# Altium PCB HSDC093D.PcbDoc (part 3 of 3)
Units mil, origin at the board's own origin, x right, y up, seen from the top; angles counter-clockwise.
Board outline 4360 x 2202.42 mil, 6 copper layers (Top Layer, GND1, VCC1, VCC2, GND2, Bottom Layer), stack 84.434 mil thick; 280 components, 182 nets, 800 pads, 401 vias.
Unrouted connection lines stored in the file: 5.
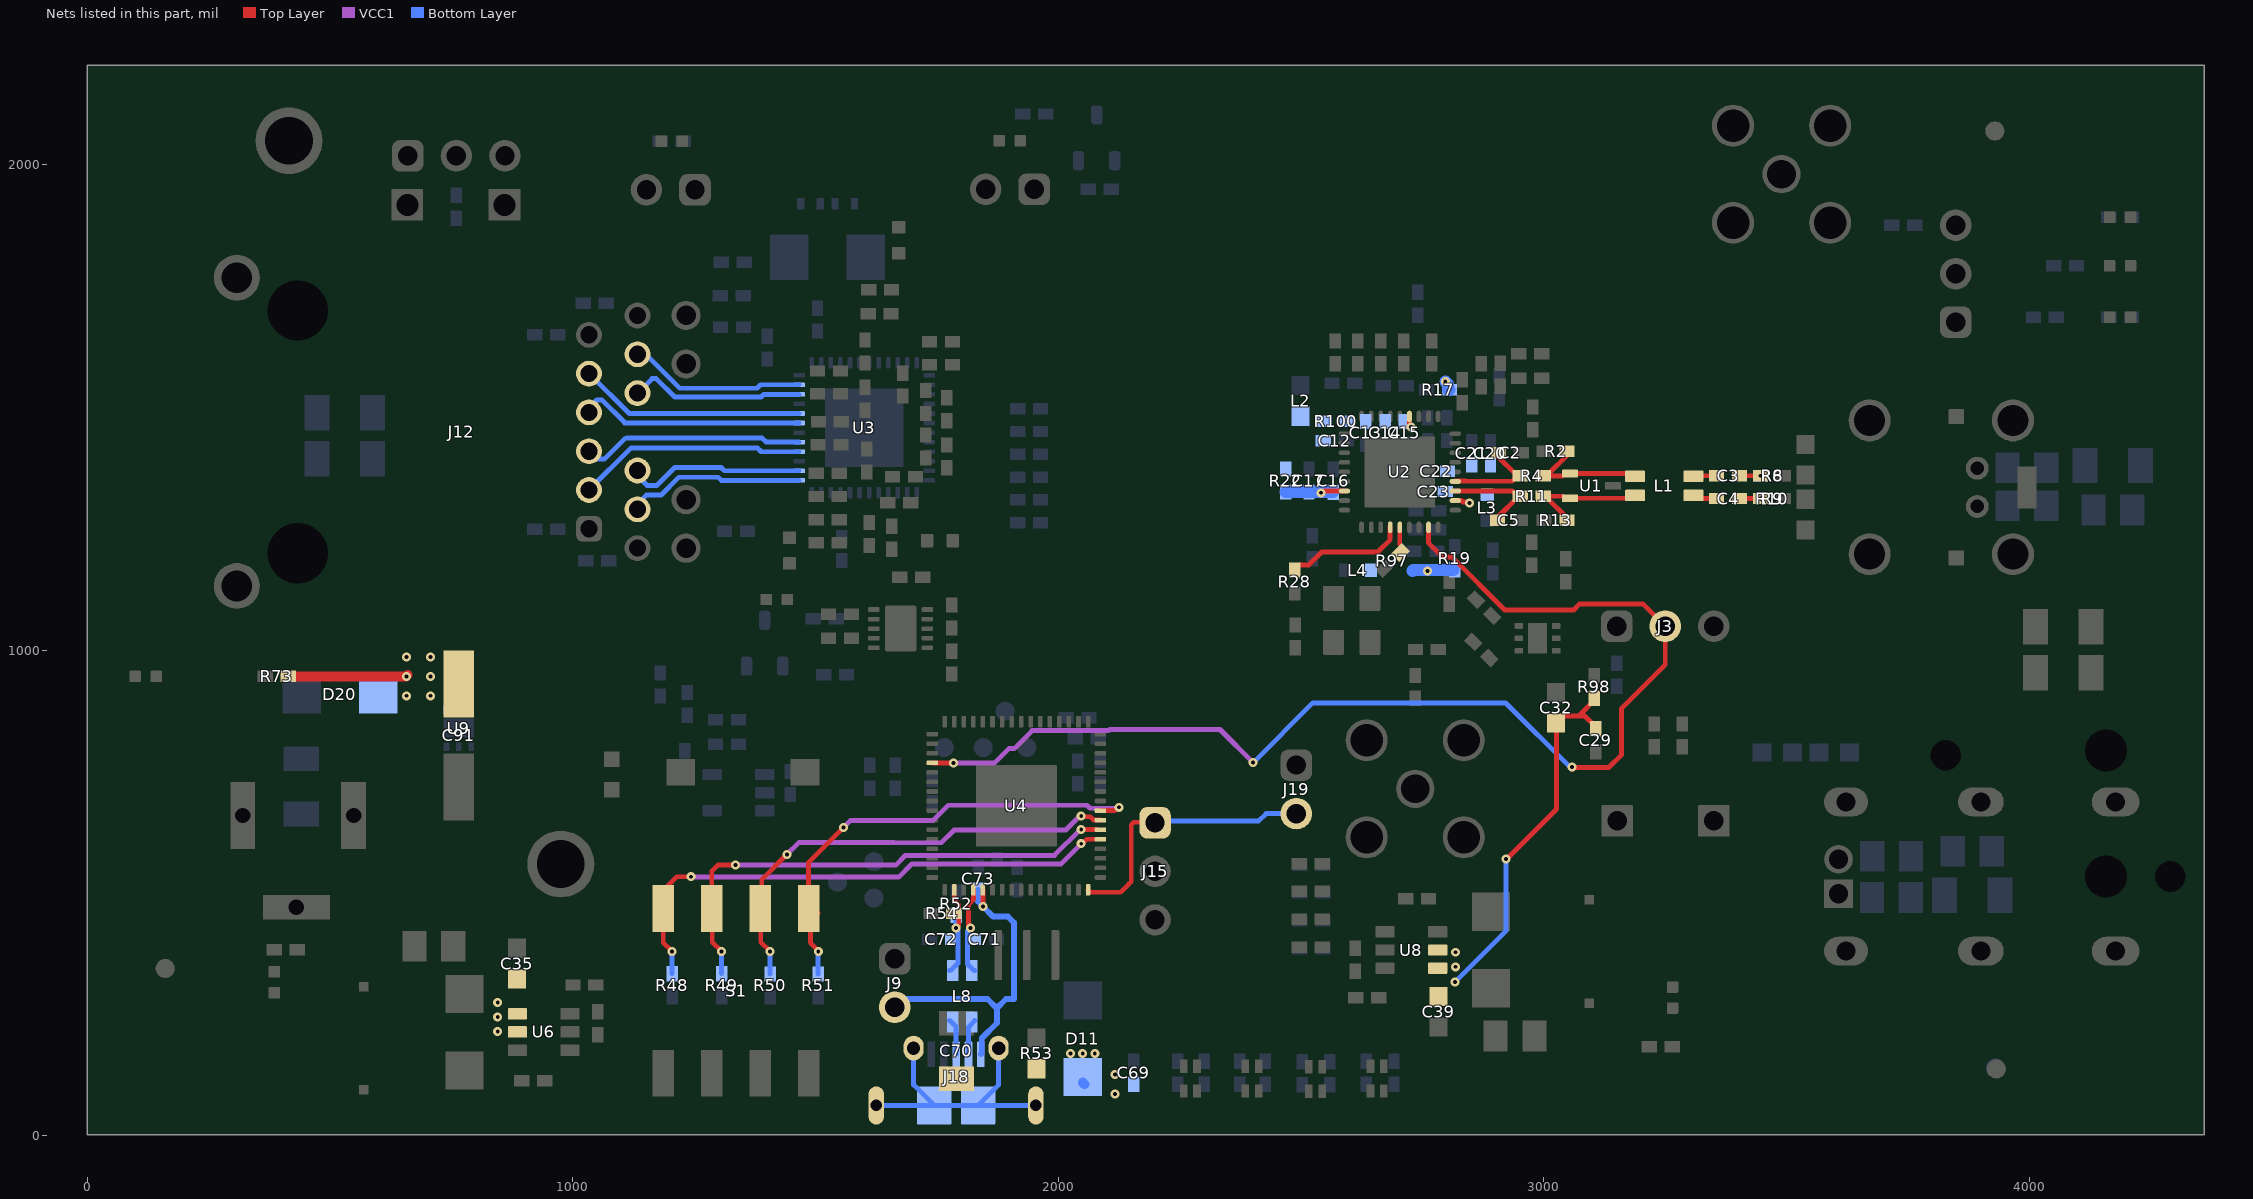
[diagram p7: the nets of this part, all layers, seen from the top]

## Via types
v1: diameter 18.5, hole 7.87, Top Layer to Bottom Layer, tented both sides, 357 vias
v2: diameter 19.68, hole 7.87, Top Layer to Bottom Layer, 25 vias
v3: diameter 17.72, hole 7.87, Top Layer to Bottom Layer, tented both sides, 8 vias
v4: diameter 19.68, hole 7.87, Top Layer to Bottom Layer, tented both sides, 7 vias
v5: diameter 157.48, hole 125.98, Top Layer to Bottom Layer, 4 vias

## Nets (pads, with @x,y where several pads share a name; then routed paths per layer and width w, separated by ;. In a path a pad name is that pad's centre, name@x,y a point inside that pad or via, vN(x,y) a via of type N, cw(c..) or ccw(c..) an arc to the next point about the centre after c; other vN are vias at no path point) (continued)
SBWTDIO: J15.1 J19.2 U4.64 | length 567.6
  Top Layer w10: U4.64@2061.06,506.77 2065.84,502 2128.29,502 2144.13,517.84 2144.13,518.13 2150,524 2150,641 2154,645 ; 2155,646 J15.1@2188.37,646.38
  Bottom Layer w10: J15.1@2188.37,646.38 2190.89,648.9 2412.75,648.9 2427.85,664 J19.2@2490,664 2491,664 J19.2@2492,663
SW1: R48.1 S1.8 U4.5 | length 1049.9
  Top Layer w10: S1.8@1186,435 1186,398.33 v1(1204.33,380) ; S1.8@1187,501 1187,507 1214,534 v1(1243,534) ; v1(2047,602) 2049.3,602 2058.4,611.1 U4.5@2079.84,611.1
  VCC1 w10: v1(1243,534) 1243.87,533.13 1671.13,533.13 1698.13,560.13 1782.39,560.13 1782.52,560 2005,560 v1@2046,601
  Bottom Layer w10: R48.1@1204.33,334.08 v1(1204.33,380)
SW2: R49.1 S1.7 U4.6 | length 977.2
  Top Layer w10: S1.7@1286,501 1286,545.57 1298.43,558 v1(1335,558) ; S1.7@1287,429 1287,399.33 v1(1306.33,380) ; v1(2047,631) 2047.11,630.89 U4.6@2079.84,630.89
  VCC1 w10: v1(1335,558) 1335.13,557.87 1504.28,557.87 1504.4,558 1665,558 1685,578 1991.71,578 2044.71,631 v1(2047,631)
  Bottom Layer w10: R49.1@1306.11,334.08 1306.22,334.19 1306.22,379.22 v1@1307,380
SW3: R50.1 S1.6 U4.7 | length 902
  Top Layer w10: S1.6@1389,438 1387,436 1387,399.11 v1(1406.11,380) ; S1.6@1389,495 1389,528 v1(1441,580) ; v1(2047,659) 2048.63,657.37 2065.86,657.37 2072.23,651 U4.7@2087,651
  VCC1 w10: v1(1441,580) 1465.13,604.13 1661.58,604.13 1661.84,603.87 1758.87,603.87 1785,630 1830.12,630 1830.2,629.92 2014.63,629.92 2043.71,659 v1(2047,659)
  Bottom Layer w10: R50.1@1406.11,333.62 v1(1406.11,380)
SW4: R51.1 S1.5 U4.8 | length 924.2
  Top Layer w10: S1.5@1486,438 1489,435 1489,397.97 1505.33,381.64 v1(1505.33,380) ; S1.5@1487,488 1485,490 1485,563 v1(1557,635) ; S1.5@1504,460 S1.5@1505.33,458.67 ; U4.8@2086.65,670.16 2115.86,670.16 2122.7,677 v1(2125,677) v1@2126,677
  VCC1 w10: v1(1557,635) 1571.87,649.87 1741.87,649.87 1773.13,681.13 2058.87,681.13 2065,675 v1@2125,675
  Bottom Layer w10: R51.1@1504.92,333.62 1505.13,333.83 1505.13,379.13 v1@1506,380
TD_A_N: J12.9 U3.2 | length 370.6
  Bottom Layer w10: J12.9@1133,1370.63 1133,1359.55 1152.55,1340 1173.08,1340 1210,1376.92 1305,1376.92 1311.88,1370.04 U3.2@1466.3,1370.04
TD_A_P: J12.8 U3.1 | length 369.8
  Bottom Layer w10: J12.8@1133,1290.71 1133,1301.63 1151.37,1320 1181.37,1320 1218.28,1356.92 1298.9,1356.92 1305.46,1350.35 U3.1@1466.3,1350.35
TD_B_N: J12.3 U3.5 | length 461.4
  Bottom Layer w10: J12.3@1033,1410.39 1049.19,1394.2 1064.81,1394.2 1107.73,1437.13 1111.37,1437.13 1111.53,1437.28 1390,1437.28 1397.88,1429.41 1434.46,1429.41 1434.46,1429.09 U3.5@1466.3,1429.09
TD_B_P: J12.2 U3.4 | length 472.7
  Bottom Layer w10: J12.2@1033,1330.47 1119.81,1417.28 1379.87,1417.28 1387.4,1409.76 1387.4,1409.41 U3.4@1466.3,1409.41
TD_C_N: J12.5 U3.8 | length 467.3
  Bottom Layer w10: J12.5@1033,1570.24 1033.96,1570.24 1116.05,1488.15 U3.8@1466.3,1488.15
TD_C_P: J12.4 U3.7 | length 470
  Bottom Layer w10: J12.4@1033,1490.31 1033,1499.64 1049.58,1516.22 1059.69,1516.22 1106.13,1469.78 1106.13,1468.46 U3.7@1466.3,1468.46
TD_D_N: J12.11 U3.11 | length 365.3
  Bottom Layer w10: J12.11@1133,1610 1150,1610 1220,1540 1379.11,1540 1386.32,1547.2 U3.11@1466.3,1547.2
TD_D_P: J12.10 U3.10 | length 363.6
  Bottom Layer w10: J12.10@1133,1530.08 1162.93,1560.01 1171.7,1560.01 1209.59,1522.13 1387.37,1522.13 1392.77,1527.52 U3.10@1466.3,1527.52
TRD1_N: L1.4 R2.1 R4.1 U1.1 | length 243.7
  Top Layer w10: R4.1@2995,1360 2999.59,1364.59 3010.26,1364.59 R2.1@3047.99,1402.32 ; R4.1@2998.78,1359.71 3010.26,1359.71 3038.71,1359.71 3043.59,1364.59 U1.1@3053.71,1364.59 L1.4@3169.98,1364.59
TRD1_P: L1.1 R11.1 R13.2 U1.2 | length 228.9
  Top Layer w10: R11.1@2998.78,1317.67 3007.11,1317.67 3039.33,1317.67 3043.59,1313.41 U1.2@3053.71,1313.41 L1.1@3169.98,1313.41 ; R11.1@3007.11,1313.41 R13.2@3046.68,1273.84
TRD2_N: C3.2 L1.3 | length 58.1
  Top Layer w10: L1.3@3301.04,1356.69 L1.3@3304.35,1360 ; L1.3@3302.35,1360 C3.2@3355.76,1360
TRD2_P: C4.2 L1.2 | length 58.5
  Top Layer w10: L1.2@3303.04,1313.32 3303.35,1313 C4.2@3355.76,1313 ; L1.2@3312.85,1322.27 L1.2@3316.85,1318.27
TRD3_N: C3.1 R6.1 R8.1 | length 42.4
  Top Layer w10: C3.1@3404,1360 v1(3446,1360) R6.1@3446.38,1360
TRD3_P: C4.1 R9.1 R10.1 | length 45.4
  Top Layer w10: C4.1@3403,1313 v1(3446,1313) R10.1@3446.38,1313 ; R10.1@3449,1313 R10.1@3451.01,1313
TRD_N: C2.2 R4.2 U2.13 | length 199.6
  Top Layer w10: U2.13@2817.24,1348.72 2838.97,1348.72 ; 2839,1348.69 2934.69,1348.69 2944.93,1358.93 R4.2@2944.93,1359.71 ; C2.2@2902.32,1402.32 R4.2@2944.93,1359.71 ; R4.2@2951.54,1359.71 R4.2@2944.93,1359.71
TRD_P: C5.1 R11.2 U2.12 | length 203.1
  Top Layer w10: U2.12@2815.03,1328.69 2934.31,1328.69 2945.33,1317.67 R11.2@2948.27,1317.67 ; C5.1@2904.44,1273.84 R11.2@2948.27,1317.67 ; R11.2@2951.54,1317.67 R11.2@2948.27,1317.67
USB1_D_N: C71.2 L8.4 U4.52 | length 181.8
  Top Layer w10: v1(1819.02,428.19) 1814.79,432.41 1814.79,476.96 1824.84,487.01 U4.52@1824.84,506.77
  Bottom Layer w10: v1(1819.02,428.19) 1812.81,421.98 1812.81,353.75 1823.55,343.01 1825.11,341.46 L8.4@1828,341
USB1_D_P: C72.2 L8.1 R52.2 R54.1 U4.50 | length 208.1
  Top Layer w10: U4.50@1785.47,506.77 1785.47,486.3 1794.79,476.98 1794.79,433.78 v1(1789.2,428.19)
  Bottom Layer w10: L8.1@1776,341 1779.05,341.46 1780.53,342.94 1792.81,355.22 1792.81,424.58 v1(1789.2,428.19) R52.2@1789.2,454.57
USB_D_N: J18.2 L8.3 | length 75.1
  Bottom Layer w10: J18.2@1814.79,168.15 1814.79,223.9 1823.48,233.17 L8.3@1828,238
USB_D_P: J18.3 L8.2 | length 75.3
  Bottom Layer w10: L8.2@1776,238 1780.72,233.26 1789.2,224.76 J18.3@1789.2,168.15
USB_VBUS: C73.1 J9.2 J18.1 U4.53 | length 703
  Top Layer w10: v1(1844.53,472.79) U4.53@1844.53,506.77
  Bottom Layer w12: J9.2@1646,262 1666,282 1854,282 1873,263 ; C73.1@1834.48,506.38 1834.48,482.83 v1(1844.53,472.79) 1865.59,451.72 1896.28,451.72 ; J18.1@1840.39,168.15 1842.26,170.02 1842.26,201.17 1873.59,232.5 1873.59,262.41 1873,263 ; 1896,452 1896.28,451.72 ; 1873,263 1892,282 1908.65,282 1908.65,439.35 1896.28,451.72
USBGND: C70.2 J18.6 J18.7 J18.8 J18.9 J18.10 J18.11 R53.1 | length 600.9
  Bottom Layer w10: J18.7@1624.83,62.83 J18.8@1743.93,62.83 ; J18.6@1701.61,180.94 1701.61,105.16 J18.8@1743.93,62.83 ; J18.11@1876.8,180.94 1876.8,105.16 J18.9@1834.48,62.83 ; J18.10@1954,64 1952.83,62.83 J18.9@1834.48,62.83 ; J18.8@1743.93,62.83 J18.9@1834.48,62.83
VDD1P0: L4.2 R17.2 R19.2 | length 135.8
  Bottom Layer w10: 2721.98,1166 2723.98,1164 2729,1164 ; 2745,1164 v1(2760,1164)
  Bottom Layer w25: 2729,1164 2731,1166 2745,1166 v1@2765,1166 ; v1@2760,1166 v1@2765,1166 ; v1(2797,1554) 2802.37,1548.63 2802.37,1537.69 2803.06,1537 R17.2@2805.62,1537 ; R19.2@2814,1166 v1@2765,1166
VDDA3P3: C20.1 C21.1 C22.1 C23.1 L3.2 U2.11 | length 25.9
  Top Layer w10: U2.11@2826,1309 2829.96,1309 2833.33,1305.63 2845.37,1305.63 v1(2847,1304)
  Bottom Layer w10: C23.1@2794,1323 C23.1@2796,1325
VDDIO: C12.1 L2.2 R22.2 R100.2
VDDIO1: C13.1 C14.1 C15.1 R100.1 U2.22 | length 16.2
  Top Layer w10: U2.22@2723.08,1475.19 2723.08,1465.88 2726.29,1462.67 v1(2726.29,1460.37)
VDDIO2: C16.1 C17.1 R22.1 U2.34 | length 151.2
  Top Layer w10: v1@2540.5,1324.38 v1(2540.88,1324.76) v1@2542.25,1326.13 ; v1@2542,1324 2542.42,1324 2546.88,1328.46 U2.34@2589.14,1328.46
  VCC1 w10: v1@2541,1326 v1@2542.24,1324.76
  Bottom Layer w10: R22.1@2469,1326 R22.1@2469.41,1326.41
  Bottom Layer w25: R22.1@2468.41,1326.41 C17.1@2516.14,1326.41 2540.88,1326.41 C16.1@2565.84,1326.41
Vin: C29.1 C32.1 C35.1 C39.1 C69.1 C91.1 D11.1 D20.1 R73.1 R98.2 U6.4 U6.5 U8.4 U8.5 U9.4 U9.5 U9.6 | length 1019.7
  Top Layer w10: v1@2923,572 2925,572 3026,673 C32.1@3026,848 ; C32.1@3025,850.5 3025,851.3 3038.7,865 3071.56,865 ; R98.2@3105,900 3105,898.44 3071.56,865 ; C29.1@3107,838.62 3107,842.56 3084.56,865 3071.56,865
  Top Layer w20: R73.1@413.62,946.46 656.46,946.46 v1@660,950
  Bottom Layer w10: v1@2817,318 2817.75,318 2922.12,422.37 v1(2922.12,570.37)
  Bottom Layer w20: D11.1@2050,110 D11.1@2053.64,106.36
  other v1: 2116.88,86.63 2116.88,126.63 2025,170 2050,170 2075,170 845,215 845,245 845,275 2817.12,317.37 2818.12,348.37 2818.12,378.37 656.88,906.63 706.88,906.63 656.88,946.63 706.88,946.63 656.88,986.63 706.88,986.63
Wake_720: J3.2 U2.8 U4.36 | length 2491.6
  Top Layer w10: U4.36@1740.2,768.58 1740.47,768.31 1782.69,768.31 v1@1784,767 ; v1@2402,768 v1@2402,769 ; U2.8@2762.12,1247.42 2762.12,1221.59 2791.06,1192.65 2810.35,1192.65 2919.61,1083.39 3061.1,1083.39 3073.06,1095.35 3204.65,1095.35 J3.2@3250,1050 3250,971 3160,881 3160,785 3134,759 3063,759 v1@3060,756
  VCC1 w10: v1(1784,768) 1868.12,768 1897.99,797.87 1908.87,797.87 1945.87,834.87 2103.58,834.87 2105.84,837.13 2332.87,837.13 v1(2401,769)
  Bottom Layer w10: v1(2401,769) 2524,892 2921,892 v1@3057,756
  other v1: 3058,760
XI: R97.2 U2.5 | length 53.7
  Top Layer w10: U2.5@2703.06,1254.24 2703.06,1218.54 2707.49,1214.12 2707.49,1204.49 R97.2@2706,1203
XO: R28.2 U2.4 | length 250.2
  Top Layer w10: R28.2@2487,1166 2487,1169.56 2493.81,1176.37 2516.2,1176.37 2542.7,1202.88 2657.88,1202.88 2683.38,1228.38 U2.4@2683.38,1254.24
pads on no net: FID1.1 FID2.1 FID3.1 FID4.1 FID5.1 FID6.1 J5.MH1 J5.MH2 J5.MH3 J5.MH4 J12.ALIGN1 J12.ALIGN2 J18.4 U2.19 U2.20 U3.13 U3.18 U3.20 U3.21 U3.22 U3.23 U3.39 U3.40 U3.48 U3.49@1546.22,1404.68 U3.49@1546.22,1458.62 U3.49@1546.22,1512.56 U3.49@1600.16,1404.68 U3.49@1600.16,1458.62 U3.49@1600.16,1512.56 U3.49@1654.09,1404.68 U3.49@1654.09,1458.62 U3.49@1654.09,1512.56 U4.9 U4.10 U4.12 U4.13 U4.26 U4.27 U4.32 U4.33 U4.38 U4.41 U4.47 U4.48 U4.60 U4.61 U4.62 U4.63 U7.3 U7.7 U9.7@747.28,840 U9.7@782.72,840 U10.5 U10.7@2987,1007.28 U10.7@2987,1042.72

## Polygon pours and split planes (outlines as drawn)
+3V3 on VCC1 "VCC1_+3V3_P393" (solid, remove dead copper, pour order 393): 1220,2150 4314,2150 4314,1600 3500,1600 3500,45 1205,45 1205,2135
+3V3_REG on VCC1 "VCC1_+3V3_REG_P378" (solid, remove dead copper, pour order 378): 1605,1875 1630,1900 1630,1940 1640,1950 1724,1950 1725,1949 1725,830 2170,830 2255,745 2255,300 2235,280 1000,280 950,330 435,330 420,345 420,545 755,880 755,1860 755,2150 1200,2150 1200,1875
+2V5_REG on VCC1 "VCC1_+2V5_REG_P373" (solid, remove dead copper, pour order 373): 3260,160 3240,140 2815,140 2796,159 2796,237 2852,293 2852,395 2834,413 2287,413 2266,434 2266,759 2184,841 1699,841 1575,965 1575,1125 1600,1150 2370,1150 2525,995 2560,960 2560,620 2580,600 3180,600 3260,520
Vin on VCC1 "VCC1_VIN_P367" (solid, remove dead copper, pour order 367): 2830,400 2400,400 2310,400 2280,370 2280,290 2240,250 980,250 930,300 410,300 395,315 395,550 735,890 735,980 715,1000 40,1000 40,40 2760,40 2780,60 2780,240 2840,300 2840,390
+3V3_867 on VCC1 "VCC1_+3V3_867_P377" (solid, remove dead copper, pour order 377): 1800,1675 1825,1650 1825,1200 1800,1175 1525,1175 1500,1200 1500,1650 1525,1675
GND867 on VCC1 "VCC1_GND867_P388" (solid, remove dead copper, pour order 388): 480,1820 40,1820 40,1080 480,1080
GND on Top Layer "TOP_LAYER_GND_P403" (solid, remove dead copper, pour order 403): 4332.53,16 4332.53,241 3507.53,241 3507.53,1616 4332.53,1616 4332.53,2166 32.53,2166 32.53,1966 1357.53,1966 1357.53,966 32.53,966 32.53,16
+1V0_REG on Top Layer "TOP_LAYER_+1V0_REG_P375" (solid, remove dead copper, pour order 375): 1695,1060 1940,1060 2065,1185 2065,1915 1980,2000 1825,2000 1800,1975 1800,1922 2034,1723.1 2034,1579 1695,1240
+3V3 on Top Layer "TOP_LAYER_+3V3_P409" (solid, pour order 409): 3214,832 3298,832 3298,871 3270,899 3270,923 3263,930 3220,930 3214,924
+2V5_REG on Top Layer "TOP_LAYER_+2V5_REG_P376" (solid, remove dead copper, pour order 376): 1435,1200 1470,1200 1490,1180 1590,1180 1635,1135 1635,1060 1565,1060 1565,1090 1500,1090 1435,1155
+3V3_867 on Top Layer "TOP_LAYER_+3V3_867_P359" (solid, remove dead copper, pour order 359): 1678.44,1780 1689.44,1791 1702,1791 1702,1833 1678.44,1833 1620,1833 1620,1614.68 1576.58,1614.68 1576.58,1531.81 1589.77,1518.62 1613.37,1518.62 1620,1511.99 1620,1390.49 1615.08,1385.57 1593.19,1385.57 1593.19,1345.41 1598.6,1340 1636.69,1340 1660.31,1363.62 1660.31,1427.33 1738.17,1427.33 1738.17,1490 1660.31,1490 1661.38,1646.08 1678.44,1663.14
+1V0_867 on Top Layer "TOP_LAYER_+1V0_867_P343" (solid, remove dead copper, pour order 343): 1520,1493.03 1520,1483.21 1525,1478.21 1525,1413.19 1520,1408.19 1488.54,1408.19 1484.59,1412.14 1484.59,1487.62 1490,1493.03
NetR60_1 on Top Layer "TOP_LAYER_NETR60_1_P335" (solid, remove dead copper, pour order 335): 1063.04,231.99 1076.82,245.77 1077.01,322.39 1072.86,326.53 1035.85,326.53 1032.01,322.69 1032.01,283.61 1016.8,268.41 972.92,268.41 965.8,261.3 965.8,238.55 972.36,231.99
Vin on Top Layer "TOP_LAYER_VIN_P329" (solid, remove dead copper, pour order 329): 842.34,197.66 835,205 835,299.53 873.91,338.44 897.51,338.44 897.51,337.52 907.38,327.66 907.38,203.03 902.01,197.66
Vin on Top Layer "TOP_LAYER_VIN_P324" (solid, remove dead copper, pour order 324): 2752.66,390.46 2753.25,390.46 2759.29,396.5 2823.5,396.5 2835,385 2835,301.87 2794.2,262.58 2760.32,262.58 2752.66,270.24
+3V3_REG on Top Layer "TOP_LAYER_+3V3_REG_P384" (solid, remove dead copper, pour order 384): 1651,1860 1707,1860 1725,1878 1725,1924 1710,1939 1665,1939 1651,1925
+1V0_867 on Top Layer "TOP_LAYER_+1V0_867_P361" (solid, remove dead copper, pour order 361): 1660,1315.04 1607.53,1315.31 1589.14,1296.93 1589.14,1257.56 1598.98,1247.72 1628.98,1247.72 1644.57,1232.13 1683.16,1232.13 1698.32,1247.29 1698.32,1262.15 1669.06,1291.42 1669.06,1315.02
+2V5_867 on Top Layer "TOP_LAYER_+2V5_867_P358" (solid, remove dead copper, pour order 358): 1520,1209.75 1520,1393.54 1511.06,1402.48 1489.52,1402.48 1473,1419 1473,1475.58 1492.42,1495 1508.03,1495 1520,1506.97 1520,1587.48 1515,1592.48 1461.35,1592.48 1395,1526.13 1395,1269.85 1454.83,1210.02
GND720 on Top Layer "TOP_LAYER_GND720_P357" (solid, remove dead copper, pour order 357): 4300,264 3517,264 3517,1139.51 3638.43,1260.94 3936.51,1260.94 3936.51,1421.04 3638.83,1421.04 3517,1542.87 3517,1611 4300,1611 4300,1147.11 4040,1147.11 4040,866.09 4300,866.09
GND on Top Layer "TOP_LAYER_GND_P339" (solid, remove dead copper, pour order 339): 980.61,199.99 975.23,205.37 972.7,205.37 972.7,222.3 975.86,225.45 1055.88,225.45 1101.37,225.45 1101.37,182.47 1025.61,182.47 1008.93,199.15 980.61,199.15
GND on Top Layer "TOP_LAYER_GND_P330" (solid, remove dead copper, pour order 330): 739.07,247.66 732.18,254.55 732.01,349.55 722.01,359.55 722.01,422.86 729.88,430.73 816.07,430.73 862.93,383.88 897.86,383.88 902.01,379.74 902.01,344.8 856.19,342.66 894.34,344.55 866.82,344.55 817.01,294.74 817.01,247.66
GND on Top Layer "TOP_LAYER_GND_P323" (solid, remove dead copper, pour order 323): 2925.89,353.06 2936.71,342.24 2936.71,174.9 2922.62,160.81 2809.8,160.81 2757.32,213.3 2757.32,245.78 2767.16,255.62 2804.7,255.62 2837.31,288.23 2837.31,343.22 2847.15,353.06
NetC88_2 on Top Layer "TOP_LAYER_NETC88_2_P321" (solid, remove dead copper, pour order 321): 3211.32,407.45 3223.13,419.26 3223.13,498.73 3222.15,498.73 3211.32,509.56 3217.23,503.5 3215.66,503.5 3194.33,524.83 2759.29,524.83 2757.32,522.86 2757.32,410.15 2760.01,407.45
Vin on Top Layer "TOP_LAYER_VIN_P398" (solid, pour order 398): 3039,838 3053,824 3117,824 3118,825 3118,879 3115,882 3115,915 3114,916 3086,916 3042,872 3010,872 3007,869 3007,832 3033,832
NetC88_1 on Top Layer "TOP_LAYER_NETC88_1_P322" (solid, remove dead copper, pour order 322): 2654.87,405.58 2650.3,410.15 2650.3,496.76 2664.08,510.54 2726.28,510.54 2731.28,505.54 2731.28,432.08 2704.79,405.58
NetR70_1 on Top Layer "TOP_LAYER_NETR70_1_P325" (solid, remove dead copper, pour order 325): 2592.22,351.19 2600.13,359.1 2692.22,359.1 2696.28,355.03 2696.28,330.58 2690.7,325 2647.56,325 2631.28,303.63 2631.28,262.36 2600.44,262.36 2592.22,270.58
GND on Top Layer "TOP_LAYER_GND_P336" (solid, remove dead copper, pour order 336): 725,645 695,675 695,825 723.14,853.14 806.86,853.14 835,825 835,674.92 804.6,645
NetC82_1 on Top Layer "TOP_LAYER_NETC82_1_P333" (solid, remove dead copper, pour order 333): 919.51,103.39 924.76,98.13 1008.04,98.13 1017.01,107.1 1017.01,191.02 1014.27,193.76 961.32,193.76 919.51,151.94
NetC82_2 on Top Layer "TOP_LAYER_NETC82_2_P327" (solid, remove dead copper, pour order 327): 457.01,77.33 444.67,77.33 439,83 439,164 465.26,190.26 905.99,190.26 912.3,183.95 912.3,92.09 897.53,77.33
+2V5_REG on Top Layer "TOP_LAYER_+2V5_REG_P351" (solid, remove dead copper, pour order 351): 3216.16,349.23 3233.4,331.99 3233.4,170.12 3225.08,161.79 2963.32,161.79 2953.4,170.29 2943.4,180.29 2943.4,337.54 2955.1,349.23
+3V3_REG on Top Layer "TOP_LAYER_+3V3_REG_P352" (solid, remove dead copper, pour order 352): 435.24,243.97 418,261.21 418,395.09 454.32,431.41 688.08,431.41 698,422.91 708,412.91 708,255.66 696.31,243.97
+1V0_867 on Top Layer "TOP_LAYER_+1V0_867_P360" (solid, remove dead copper, pour order 360): 1667.6,1555.25 1746.72,1555.25 1758.19,1566.72 1758.19,1657.51 1757.84,1657.51 1751.81,1663.54 1698.8,1663.54 1667.6,1632.35
USBGND on Top Layer "TOP_LAYER_USBGND_P365" (solid, remove dead copper, pour order 365): 1600,19.97 1600,142 1982.32,142 1982.32,22.01
Vin on Top Layer "TOP_LAYER_VIN_P369" (solid, remove dead copper, pour order 369): 800,880 590,880 580,890 580,985 595,1000 800,1000
GND on Top Layer "TOP_LAYER_GND_P401" (solid, remove dead copper, pour order 401): 4100,1090 4105,1095 4245,1095 4250,1090 4250,915 4245,910 4105,910 4100,915
no net on Bottom Layer "BOTTOM_LAYER_NONET_P414" (solid, remove dead copper, pour order 414): 36,2167 4316,2167 4316,47 36,47 36,977 546,977 546,1977 36,1977
GND on Bottom Layer "BOTTOM_LAYER_GND_P412" (solid, remove dead copper, pour order 412): 40,2160 4320,2160 4320,40 40,40 40,970 550,970 550,1970 40,1970
VDDIO1 on Bottom Layer "BOTTOM_LAYER_VDDIO1_P353" (solid, pour order 353): 2579,1462 2587,1454 2735,1454 2738,1457 2738,1485 2733,1490 2627,1490 2621,1484 2583,1484 2579,1480
VDDIO on Bottom Layer "BOTTOM_LAYER_VDDIO_P364" (solid, pour order 364): 2487,1503 2514,1503 2532,1485 2561,1485 2566,1480 2566,1418 2560,1412 2504,1412 2481,1389 2481,1358 2479,1356 2455,1356 2453,1358 2453,1400 2480,1427 2480,1498
NetC10_1 on Bottom Layer "BOTTOM_LAYER_NETC10_1_P362" (solid, pour order 362): 2795,1300 2828,1267 2828,1200 2819,1191 2767,1191 2763,1195 2763,1293 2770,1300
VDD1P0 on Bottom Layer "BOTTOM_LAYER_VDD1P0_P385" (solid, remove dead copper, pour order 385): 2620,1260 2610,1250 2610,1225 2595,1210 2595,1170 2615,1150 2825,1150 2845,1170 2845,1215 2840,1220 2810,1220 2805,1215 2805,1190 2800,1185 2735,1185 2660,1260
VDDA3P3 on Bottom Layer "BOTTOM_LAYER_VDDA3P3_P381" (solid, remove dead copper, pour order 381): 2779.14,1383.09 2904.14,1383.37 2907.14,1380.37 2907.04,1302.37 2862.37,1302.37 2850.54,1290.54 2778.14,1290.54
NetC9_1 on Bottom Layer "BOTTOM_LAYER_NETC9_1_P368" (solid, pour order 368): 2702,1558 2734,1558 2772,1548 2772,1529 2812,1489 2812,1463 2810,1461 2750,1461 2746,1465 2746,1494 2741,1494 2702,1533
+1V0 on Bottom Layer "BOTTOM_LAYER_+1V0_P400" (solid, remove dead copper, pour order 400): 2510,1210 2610,1210 2610,1145 2520,1145 2510,1155
+3V3 on Bottom Layer "BOTTOM_LAYER_+3V3_P410" (solid, remove dead copper, pour order 410): 2561,1534.84 2544,1524 2489,1524 2484,1519 2484,1501 2478,1495 2444,1495 2444,1565 2570,1565 2580,1555 2580,1534.84
+3V3 on Bottom Layer "BOTTOM_LAYER_+3V3_P411" (solid, remove dead copper, pour order 411): 2909,1189 2909,1291.33 2868,1291.33 2857,1280.33 2857,1214 2882,1189
GND867 on Bottom Layer "BOTTOM_LAYER_GND867_P413" (solid, remove dead copper, pour order 413): 500,1815 40,1815 40,1075 500,1075
no net on Bottom Layer "BOTTOM_LAYER_NONET_P374" (solid, remove dead copper, pour order 374): 25.69,2180 25.49,2179.8 25.49,35
Vin on Bottom Layer "BOTTOM_LAYER_VIN_P380" (solid, remove dead copper, pour order 380): 560.56,950 610.56,1000 818.2,1000 818.7,999.49 818.7,875 711.75,875 698.05,861.3 560.56,861.3
Vin on Bottom Layer "BOTTOM_LAYER_VIN_P383" (solid, remove dead copper, pour order 383): 2150,120 2080,190 2030,190 2010,170 2010,70 2160,70 2170,80 2170,120
GND on VCC2 "VCC2_GND_P396" (solid, remove dead copper, pour order 396): 25,2175 4305,2175 4305,55 25,55 25,970 550,970 550,1970 25,1970
VDD1P0 on VCC2 "VCC2_VDD1P0_P395" (solid, remove dead copper, pour order 395): 2600,1625 2625,1650 2850,1650 2875,1625 2875,1075 2850,1050 2625,1050 2600,1075
+1V0 on VCC2 "VCC2_+1V0_P394" (solid, remove dead copper, pour order 394): 1900,2150 1900,960 2595,960 2595,2150
+1V0_867 on VCC2 "VCC2_+1V0_867_P390" (solid, remove dead copper, pour order 390): 1800,1650 1825,1625 1825,1300 1800,1275 1475,1275 1450,1300 1450,1625 1475,1650
GND867 on VCC2 "VCC2_GND867_P399" (solid, remove dead copper, pour order 399): 480,1820 40,1820 40,1080 480,1080
GND on GND1 "GND1_GND_P389" (solid, remove dead copper, pour order 389): 40,2160 4320,2160 4320,40 40,40 40,970 550,970 550,1970 40,1970
GND867 on GND1 "GND1_GND867_P397" (solid, remove dead copper, pour order 397): 479.51,1820 39.51,1820 39.51,1080 479.51,1080
GND on GND2 "GND2_GND_P366" (solid, remove dead copper, pour order 366): 40,2160 40,1970 550,1970 550,970 40,970 40,40 4320,40 4320,2160
GND867 on GND2 "GND2_GND867_P402" (solid, remove dead copper, pour order 402): 480,1815 40,1815 40,1075 480,1075

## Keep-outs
Keep-Out Layer:
  text ".Layer_Name" at 577,-2103.49 h60

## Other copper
Top Layer:
  pour cut-out: 2610,1460 2810,1460 2810,1720 2529,1720 2529,1480 2509.64,1480 2486.99,1480.48 2393.76,1570 2255,1570 2255,1384 2315,1324 2405,1324 2418,1337 2610,1337
  pour cut-out: 3865,1465 3075,1465 2825,1465 2825,1210 3075,1210 3865,1210
  pour cut-out: 3550,630 4045,630 4045,445 3550,445
  text ".Layer_Name" at 577,-2103.49 h60
VCC2:
  pour cut-out: 4060,1575 3575,1575 3575,1400 3940,1400 3940,1270 3575,1270 3575,1100 4060,1100
  pour cut-out: 4275,770 4075,770 4075,300 4275,300
  pour cut-out: 4000,770 3800,770 3800,620 4000,620
  pour cut-out: 3720,770 3520,770 3520,300 3720,300
  pour cut-out: 4000,450 3800,450 3800,300 4000,300
GND1:
  pour cut-out: 4060,1575 3575,1575 3575,1400 3940,1400 3940,1270 3575,1270 3575,1100 4060,1100
  pour cut-out: 3720,770 3520,770 3520,300 3720,300
  pour cut-out: 4000,450 3800,450 3800,300 4000,300
  pour cut-out: 4000,770 3800,770 3800,620 4000,620
  pour cut-out: 4275,770 4075,770 4075,300 4275,300
GND2:
  pour cut-out: 4060,1575 3575,1575 3575,1400 3940,1400 3940,1270 3575,1270 3575,1100 4060,1100
  pour cut-out: 4000,770 3800,770 3800,620 4000,620
  pour cut-out: 3720,770 3520,770 3520,300 3720,300
  pour cut-out: 4275,770 4075,770 4075,300 4275,300
  pour cut-out: 4000,450 3800,450 3800,300 4000,300
Bottom Layer:
  pour cut-out: 1665.62,1277.38 1714,1229 2006,1229 2132,1355 2329,1355 2329,1376 2329,1415 1974,1415 1922,1363 1667,1363
  pour cut-out: 2424,1547 2447,1570 2511,1570 2798.67,1570 2801.24,1803.76 2685,1920 1962,1920 1777,1735 1777,1634.32 1752,1608.52 1752,1587 1752,1465 1939,1465 2021,1547
  pour cut-out: 3260,1480 3540,1760 3540,1900 3580,1940 3580,2020 3540,2060 3440,2060 3400,2020 3400,1940 3440,1900 3440,1820 3200,1580 2860,1580 2840,1560 2840,1480
  pour cut-out: 3895,770 3595,770 3595,1343 3538,1400 3400,1400 3396,1396 3396,1264 3400,1260 3447,1260 3478,1229 3478,482 3520,440 3520,300 3895,300 4320,300 4320,440 3895,440 3895,645 4320,645 4320,770
  pour cut-out: 3575,1575 4070,1575 4185,1460 4185,1215 4070,1100 3575,1100
  text ".Layer_Name" at 577,-2103.49 h60

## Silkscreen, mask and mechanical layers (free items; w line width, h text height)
Top Overlay:
  circle w10: c1115,897 r5
  circle w10: c1115,897 r10
  lines w5.91: 2533,304 2533,298 2546,285 2576,285 ; 2850,1213 2850,1303 2863,1316 2915,1316 ; 3062,778 3062,906 3076,920
  lines w10: 960,897 1000,897 ; 980,877 980,882 980,917 ; 1025,897 1110,897 ; 1093.79,875.79 ccw(c1115,897) 1093.79,918.21 ; 1145,897 1210,897 ; 1240,897 1280,897 ; 1581,1150 1607,1176 1607,1185 ; 1680,1605 1680,1650 1701,1671 ; 1690,1196 1700,1186 1854,1186 ; 2060,480 2115,480 2115,535 ; 2550,1235 2575,1210 2660,1210 ; 3070,1235 3115,1190 3170,1190 ; 3155,955 3355,955 ; 3450,1233 3450,1248 3461,1259 3461,1285
  text "720 Supply" at 1380,2020 h78.74
  text "3V3" at 1340,1925 h78.74
  text "1V0" at 1645,1925 h78.74
  text "MDC" at 975,1896 h78.74 r90
  text "GND" at 340,1895 h78.74
  text "MDIO" at 586,1884 h78.74 r90
  text "LED0" at 3946,1869 h78.74
  text "SL" at 3665,1855 h78.74
  text "PHY" at 1917,1842 h78.74
  text "PHY" at 1220,1840 h78.74
  text "CLK OUT" at 3310,1830 h78.74 r90
  text "LED1" at 3945,1771 h78.74
  text "LED0" at 3945,1671 h78.74
  text "MA" at 3665,1650 h78.74
  text "1V0" at 1360,1020 h78.74
  text "PU" at 3094,1009 h35.43 r90
  text "GND" at 3454,997 h35.43 r90
  text "5..30 VDC" at 960,947 h78.74
  text "WAKE" at 3150,885 h78.74
  text "MSP_RST" at 2235,830 h78.74
  text "INH" at 3300,711 h78.74
  text "INT" at 3099,710 h78.74
  text "CLK IN" at 2960,640 h78.74 r90
  text "RST" at 2255,630 h35.43
  text "RESET" at 1235,595 h78.74
  text "V+" at 775,535 h78.74
  text "GND" at 3180,535 h35.43
  text "TST" at 2255,530 h35.43
  text "GND" at 2255,430 h35.43
  text "PROG" at 2090,325 h78.74
  text "3V3" at 230,290 h78.74
  text "USB" at 1716,285 h78.74
  text "2V5" at 3300,270 h78.74
  text "MODE" at 2221,78 h30 r90
  text "SQI" at 2483,76 h30 r90
  text "CONF" at 2352,74 h30 r90
  text ".Layer_Name" at 577,-2103.49 h35.43
Bottom Overlay:
  lines w5.91: 2499,1280 2546,1280 2580,1280 ; 2580,1279 2581,1279 2588,1272
  text "DP83TG720EVM-MC / HSDC093" at 4280,946 h78.74
  text "Rev. 5.0 B RGMII" at 4173,880 h72.83
  text ".Layer_Name" at 577,-2103.49 h35.43
Top Paste:
  text ".Layer_Name" at 577,-2103.49 h60
Bottom Paste:
  text ".Layer_Name" at 577,-2103.49 h60
Top Solder:
  region: 3535,1592 4300,1592 4300,1611 3536,1611 3535,1610
  region: 3500,1543 3480,1543 3480,1644 3481,1645 4300,1645 4300,1625 3500,1625
  region: 3517,1543 3535,1525 3535,1611 3517,1611
  region: 3500,1140 3480,1140 3480,225 3500,225
  region: 3536,285 3517,285 3517,1139 3534,1156
  region: 3517,264 3517,285 4300,285 4300,264
  region: 3500,250 3500,225 4300,225 4300,250
  text ".Layer_Name" at 577,-2103.49 h60
  text ".Layer_Name" at 577,-2103.49 h60
Bottom Solder:
  text ".Layer_Name" at 577,-2103.49 h60
Drill Guide:
  text ".Layer_Name" at 577,-2103.49 h60
M1 Board Outline:
  lines w10: 0,0 4360,5 4360,2205 0,2205 0,0
  text ".Layer_Name" at 577,-2103.49 h60
M2 Board Dimensions:
  rectangle: 125,-1645 500,-1520
  rectangle: 0,-1520 125,-1395
  lines w7: 0,-1520 1000,-1520 ; 125,-1645 125,-1395 ; 250,-1645 250,-1395 ; 500,-1645 500,-1395 ; 750,-1645 750,-1395 ; 0,-1645 0,-1395 1000,-1395 1000,-1645 0,-1645
  text ".Layer_Name" at 577,-2103.49 h60
M3 3D STEP Top:
  text ".Layer_Name" at 577,-2103.49 h60
M4 3D STEP Bottom:
  text ".Layer_Name" at 577,-2103.49 h60
M5 Assembly Top:
  lines w10: -292,-2175.17 6308,-2175.17 ; -292,-1971.83 6310,-1971.83 ; -292,-1768.5 -292,-2378.5 3713,-2378.5 6310,-2378.5 6310,-1768.5 -291.5,-1768.5 -291.5,-2378.5 1284,-2378.5 ; 2173,-2378.5 2173,-1768.5 ; 3440,-1971.83 3440,-1768.5 ; 4280,-1971.83 4280,-1768.5 ; 4902,-2385 4902,-2182.17
  text "COMPONENTS MARKED 'DNP' SHOULD NOT BE POPULATED." at 1153.5,-1563.5 h60
  text "ASSEMBLY VARIANT:" at 1153,-1679 h60
  text ".VariantName" at 2189,-1679 h60
  text "PCB VIEWED FROM TOP SIDE" at -228.5,-1900.67 h60
  text "BOARD #:" at 2248,-1900.67 h60
  text ".PRJ_Number" at 2793.5,-1900.67 h60
  text "REV:" at 3638,-1900.67 h60
  text ".PCB_Rev" at 3929.5,-1900.67 h60
  text "SVN REV:" at 4476,-1900.67 h60
  text ".VersionControl_RevNumber" at 4982,-1900.67 h60
  text "TID #:" at 2248,-2104 h60
  text ".TID" at 2793.5,-2104 h60
  text "PLOT NAME =" at -228.5,-2309.34 h60
  text ".plot_File_Name" at 577,-2309.34 h60
  text "GENERATED    :" at 2250,-2309.34 h60
  text ".Print_Date" at 3119.5,-2309.34 h60
  text ".Print_Time" at 3848.5,-2309.34 h60
  text "TEXAS INSTRUMENTS" at 5113,-2309.34 h60
M6 Assembly Bottom:
  lines w10: -292.5,-1972.33 6309.5,-1972.33 ; -290.5,-2175.67 6309.5,-2175.67 ; 1115.5,-2385.5 1115.5,-2182.67 ; 1737.5,-1972.33 1737.5,-1769 ; 2577.5,-1972.33 2577.5,-1769 ; 3844.5,-2379 3844.5,-1769 ; 4733.5,-2379 6309,-2379 6309,-1769 -292.5,-1769 -292.5,-2379 2304.5,-2379 6309.5,-2379 6309.5,-1769
  text "COMPONENTS MARKED 'DNP' SHOULD NOT BE POPULATED." at 6102,-1563 h60
  text ".VariantName" at 5058,-1679 h60
  text "ASSEMBLY VARIANT:" at 6097,-1679 h60
  text ".VersionControl_RevNumber" at 1035.5,-1901.17 h60
  text "SVN REV:" at 1541.5,-1901.17 h60
  text ".PCB_Rev" at 2088,-1901.17 h60
  text "REV:" at 2379.5,-1901.17 h60
  text ".PRJ_Number" at 3224,-1901.17 h60
  text "BOARD #:" at 3769.5,-1901.17 h60
  text "PCB VIEWED FROM BOTTOM SIDE" at 6246,-1901.17 h60
  text ".TID" at 3224,-2104.5 h60
  text "TID #:" at 3769.5,-2104.5 h60
  text "TEXAS INSTRUMENTS" at 904.5,-2309.84 h60
  text ".Print_Time" at 2169,-2309.84 h60
  text ".Print_Date" at 2898,-2309.84 h60
  text "GENERATED    :" at 3767.5,-2309.84 h60
  text ".plot_File_Name" at 5440.5,-2309.84 h60
  text "PLOT NAME =" at 6246,-2309.84 h60
M9 Title Sheet:
  drawing of 57 lines, arcs and shapes, not listed
  text "1" at 739.84,6791.5 h70
  text "2" at 3235.5,6791.5 h70
  text "3" at 5724.84,6791.5 h70
  text "4" at 8231.51,6791.5 h70
  text "5" at 10730.5,6791.5 h70
  text "6" at 13235.5,6791.5 h70
  text "A" at -416.5,5648.5 h70
  text "A" at 14383.5,5648.5 h70
  text "B" at -416.5,3268.5 h70
  text "B" at 14383.5,3268.5 h70
  text "C" at -416.5,893.5 h70
  text "C" at 14383.5,893.5 h70
  text "PROJECT TITLE:" at 11343.5,-967.5 h45
  text ".PRJ_Title" at 11393.5,-1100.83 h70
  text "DESIGNED FOR:" at 11343.5,-1268.5 h45
  text ".PRJ_Customer" at 11393.5,-1408.5 h70
  text "D" at -416.5,-1476.5 h70
  text "D" at 14383.5,-1476.5 h70
  text "FILE NAME:" at 11343.5,-1568.5 h45
  text ".PCB_File_Name_No_Path" at 11393.5,-1688.5 h70
  text "Texas Instruments (TI) and/or its licensors do not warrant the accuracy or completeness of this specification" at 6374,-1850.34 h45
  text "ENGINEER:" at 11343.5,-1858.5 h45
  text "LAYOUT BY:" at 12848.5,-1858.5 h45
  text "or any information contained therein. TI and/or its licensors do not warrant that this design will meet" at 6329.01,-1963 h45
  text ".PRJ_Engineer" at 11393.5,-2013.49 h70
  text ".PCB_Layout" at 12899,-2013.49 h70
  text "the specifications, will be suitable for your application or fit for any particular purpose, or will operate in" at 6329.01,-2075.67 h45
  text ".Layer_Name" at 577,-2103.49 h60
  text "ALTIUM DESIGNER VERSION:" at 12848.5,-2168.5 h45
  text "an implementation. TI and/or its licensors do not warrant that the design is production worthy. You should" at 6329.01,-2188.33 h45
  text "completely validate and test your design implementation to confirm the system functionality for your application." at 6374,-2301 h45
  text ".print_Scale" at 11393.5,-2301.83 h70
  text ".Application_BuildNumber" at 12899,-2301.83 h70
  text "1" at 739.84,-2508.5 h70
  text "2" at 3235.5,-2508.5 h70
  text "3" at 5724.84,-2508.5 h70
  text "4" at 8231.51,-2508.5 h70
  text "5" at 10730.5,-2508.5 h70
  text "6" at 13235.5,-2508.5 h70
M10 Fab Notes:
  drawing of 189 lines, arcs and shapes, not listed
  text "DESIGN INFORMATION" at 12382.02,5111.17 h60
  text "MIN. TRACK WIDTH:" at 11737.46,4979.05 h60
  text "8" at 12833.7,4979.05 h60
  text "MIL" at 12988.46,4979.05 h60
  text "MIN. CLEARANCE:" at 11737.46,4854.92 h60
  text "0.2" at 12773.7,4854.93 h60
  text "mm" at 12988.46,4854.92 h60
  text "MIN. VIA PAD SIZE:" at 11737.46,4730.8 h60
  text "24" at 12803.71,4730.8 h60
  text "MIL" at 12988.46,4730.8 h60
  text "0.05mm (2MIL)" at 12432.46,4600.9 h60
  text "MINIMUM ANNULAR RING" at 11408.23,4592.67 h60
  text "EXTERNAL" at 13140.46,4592.67 h60
  text "PER" at 11608.23,4482.55 h60
  text "IPC-D-275 CLASS 2 LEVEL C" at 11828.23,4482.54 h60
  text "MIL, HOLES" at 13316.46,4382.07 h60
  text "+/-" at 12924,4373.48 h60
  text "+/-" at 13778,4373.48 h60
  text "REGISTRATION TOLERANCES:" at 11408.23,4372.42 h60
  text "METAL" at 12608,4372.42 h60
  text "5" at 13184.2,4372.42 h60
  text "3" at 14017.2,4372.42 h60
  text "MIL" at 14133.46,4372.42 h60
  text "HOLE SIZE TOLERANCE (UNLESS OTHERWISE SPECIFIED):" at 11408.23,4274.1 h60
  text "+/-" at 13778,4271.23 h60
  text "3" at 14017.2,4270.17 h60
  text "MIL" at 14133.46,4270.17 h60
  text "MATERIAL:" at 11333.46,4132.52 h60
  text "FR-4 High Tg" at 12319.9,4004 h60
  text "X" at 12175.46,3996.01 h60
  text "FR-408" at 11754.46,3991.49 h60
  text "OTHER" at 13242.46,3991.49 h60
  text "62 MIL (1.6mm) +/-10%" at 12074.56,3848.46 h60
  text "X" at 11954.46,3846.01 h60
  text "THICKNESS:" at 11408.23,3840.24 h60
  text "OTHER" at 13359.46,3840.24 h60
  text "TOLERANCE:" at 11408.23,3701.92 h60
  text "X" at 12256.46,3701.92 h60
  text "ANSI IPC-6012 TYPE 3 CLASS 2" at 12434.48,3701.92 h60
  text "OTHER +/-" at 12434.46,3557.73 h60
  text "BOW & TWIST:" at 11408.23,3412.54 h60
  text "X" at 12256.46,3412.54 h60
  text "ANSI IPC-6012 TYPE 3 CLASS 2" at 12434.48,3412.54 h60
  text "OTHER +/-" at 12434.46,3265.85 h60
  text "DRILLING:" at 11333.46,3135.23 h60
  text "NC_DRILL FILES" at 13094.46,3030.04 h60
  text "REFERENCE:" at 11408.23,3026.1 h60
  text "X" at 12065.46,3026.01 h60
  text "AS SHOWN" at 12243.46,3026.1 h60
  text "X" at 12966.46,3026.1 h60
  text "OTHER" at 13392.46,2883.85 h60
  text "PTH COPPER THICKNESS:" at 11407.91,2880.32 h60
  text "X" at 12547.14,2880.32 h60
  text "20-30 um" at 12675.14,2880.32 h60
  text "BOARD FINISH:" at 11333.46,2732.73 h60
  text "SILKSCREEN:" at 11488.68,2622.6 h60
  text "X" at 12446.46,2622.6 h60
  text "TOP" at 12563.46,2622.6 h60
  text "X" at 12956.46,2622.6 h60
  text "BOTTOM" at 13074.46,2622.6 h60
  text "SILKSCREEN COLOR:" at 11488.68,2467.41 h60
  text "X" at 12445.46,2467.41 h60
  text "WHITE" at 12563.46,2467.41 h60
  text "OTHER" at 13074.46,2467.41 h60
  text "X" at 12576.46,2323.96 h60
  text "GREEN" at 12694.46,2323.96 h60
  text "OTHER" at 13312.46,2323.96 h60
  text "SOLDER RESIST COLOR:" at 11488.68,2317.1 h60
  text "X" at 12576.46,2169.71 h60
  text "MATTE" at 12694.46,2169.71 h60
  text "SEMI-GLOSS" at 13312,2169.07 h60
  text "IMMERSION GOLD (ENIG)" at 12394.46,1996.94 h60
  text "ENEPIG" at 13732,1989.72 h60
  text "SURFACE FINISH:" at 11333.46,1988.72 h60
  text "X" at 12216.46,1988.72 h60
  text "IMM. TIN/SILVER OR EQUIV" at 11663,1851.4 h60
  text "OTHER" at 13094.46,1847.47 h60
  text "ARRAY/PANEL:" at 11333.46,1692.09 h60
  text "CUT AND TRIM PER M1 BOARD OUTLINE" at 12394.46,1683.87 h60
  text "N.C. ROUTE" at 12394.46,1547.9 h60
  text "X" at 13082.46,1547.9 h60
  text "V. SCORE" at 13260.46,1547.9 h60
  text "CERTIFICATION:" at 11333.46,1418.77 h60
  text "MATERIALS AND WORKMANSHIP FOR ALL PCBS" at 12058.46,1418.77 h60
  text "TO MEET OR EXCEED THE REQUIREMENTS OF:" at 12058.46,1324.71 h60
  text "X" at 11695.97,1196.08 h60
  text "ANSI IPC-A-600F CLASS ->" at 11823.96,1196.08 h60
  text "X" at 13471.97,1196.08 h60
  text "2" at 13581.96,1196.08 h60
  text "1" at 13266.96,1194.58 h60
  text "3" at 13935.96,1194.58 h60
  text "X" at 12507.97,1048.39 h60
  text "RoHS" at 12635.96,1048.39 h60
  text "OTHER" at 13280.36,1048.39 h60
  text "PER ORDER" at 13677.42,1048.39 h60
  text "ALL BOARDS MUST MEET OR EXCEED UL94-V0 REQUIREMENTS." at 11361,894.57 h60
  text "PCB MUST BEAR THE UL94V-0 UL REGISTERED MATERIAL ID NUMBER" at 11361,778.5 h60
  text "ADDITIONAL REQUIREMENTS:" at 11333.46,609.08 h60
  text "MICROSECTION:" at 11408.23,501.95 h60
  text "YES" at 12313.96,501.95 h60
  text "REQUIRED" at 13175.46,357.62 h60
  text "BARE BOARD ELEC. TEST:" at 11408.23,354.76 h60
  text "NONE" at 12713.96,354.76 h60
  text "X" at 13057.46,354.76 h60
  text "PER ORDER" at 13767.46,354.76 h60
  text "XX MIL VIAS REQUIRE NON-CONDUCTIVE FILL AND PLANARIZE" at 11576.38,149.82 h59
  text "XX MIL VIAS REQUIRE CONDUCTIVE FILL AND PLANARIZE" at 11584.38,45.84 h60
  text "OUTER XX MIL TRACES REQUIRE 50 OHM SINGLE-ENDED IMPEDANCE" at 11583.39,-117.54 h58
  text "LAYER 2 & 3 (INNER LAYERS) XX MIL WIDE, XX MIL SPACE / TRACES REQUIRE 100 OHM DIFFERENTIAL IMPEDANCE" at 11575.39,-353.26 h60
  text ".Layer_Name" at 577,-2103.49 h60
M11 Gerber Information:
  lines w10: -292,-2175.17 6308,-2175.17 ; -292,-1971.83 6310,-1971.83 ; -292,-1768.5 -292,-2378.5 3713,-2378.5 6310,-2378.5 6310,-1768.5 -291.5,-1768.5 -291.5,-2378.5 1284,-2378.5 ; 2173,-2378.5 2173,-1768.5 ; 3440,-1971.83 3440,-1768.5 ; 4280,-1971.83 4280,-1768.5 ; 4902,-2385 4902,-2182.17
  text "ALL ARTWORK VIEWED FROM TOP SIDE" at -228.5,-1900.67 h60
  text "BOARD #:" at 2248,-1900.67 h60
  text ".PRJ_Number" at 2793.5,-1900.67 h60
  text "REV:" at 3638,-1900.67 h60
  text ".PCB_Rev" at 3929.5,-1900.67 h60
  text "SVN REV:" at 4476,-1900.67 h60
  text ".VersionControl_RevNumber" at 4982,-1900.67 h60
  text "LAYER NAME =" at -228.5,-2103.49 h60
  text "TID #:" at 2248,-2104 h60
  text ".TID" at 2793.5,-2104 h60
  text "PLOT NAME =" at -228.5,-2309.34 h60
  text ".plot_File_Name" at 577,-2309.34 h60
  text "GENERATED    :" at 2250,-2309.34 h60
  text ".Print_Date" at 3119.5,-2309.34 h60
  text ".Print_Time" at 3848.5,-2309.34 h60
  text "TEXAS INSTRUMENTS" at 5113,-2309.34 h60
M12 Stackup:
  drawing of 399 lines, arcs and shapes, not listed
  text "Layer" at 6114.19,1057.01 h60
  text "Name" at 6524.11,1057.01 h60
  text "Material" at 7453.85,1057.01 h60
  text "Thickness" at 8313.62,1057.01 h60
  text "Constant" at 8963.45,1057.01 h60
  text "Board Layer Stack" at 9533.31,1057.01 h60
  text "Top Overlay" at 6524.11,937.01 h60
  text "Top Solder" at 6524.11,817.01 h60
  text "Solder Resist" at 7453.85,817.01 h60
  text "0.40mil" at 8313.62,817.01 h60
  text "3.5" at 8963.45,817.01 h60
  text "1" at 6114.19,697.01 h60
  text "Top Layer" at 6524.11,697.01 h60
  text "1.40mil" at 8313.62,697.01 h60
  text "Dielectric 1" at 6524.11,577.01 h60
  text "FR-4" at 7453.85,577.01 h60
  text "8.00mil" at 8313.62,577.01 h60
  text "4.2" at 8963.45,577.01 h60
  text "2" at 6114.19,457.01 h60
  text "GND1" at 6524.11,457.01 h60
  text "Copper" at 7453.85,457.01 h60
  text "1.42mil" at 8313.62,457.01 h60
  text "Dielectric 2" at 6524.11,337.01 h60
  text "10.00mil" at 8313.62,337.01 h60
  text "4.2" at 8963.45,337.01 h60
  text "3" at 6114.19,217.01 h60
  text "VCC1" at 6524.11,217.01 h60
  text "Copper" at 7453.85,217.01 h60
  text "1.40mil" at 8313.62,217.01 h60
  text "Dielectric 3" at 6524.11,97.01 h60
  text "FR-4" at 7453.85,97.01 h60
  text "40.00mil" at 8313.62,97.01 h60
  text "4.2" at 8963.45,97.01 h60
  text "4" at 6114.19,-22.99 h60
  text "VCC2" at 6524.11,-22.99 h60
  text "Copper" at 7453.85,-22.99 h60
  text "1.40mil" at 8313.62,-22.99 h60
  text "Dielectric 4" at 6524.11,-142.99 h60
  text "FR-4" at 7453.85,-142.99 h60
  text "8.00mil" at 8313.62,-142.99 h60
  text "4.2" at 8963.45,-142.99 h60
  text "5" at 6114.19,-262.99 h60
  text "GND2" at 6524.11,-262.99 h60
  text "Copper" at 7453.85,-262.99 h60
  text "1.42mil" at 8313.62,-262.99 h60
  text "Dielectric 5" at 6524.11,-382.99 h60
  text "10.00mil" at 8313.62,-382.99 h60
  text "4.2" at 8963.45,-382.99 h60
  text "6" at 6114.19,-502.99 h60
  text "Bottom Layer" at 6524.11,-502.99 h60
  text "Copper" at 7453.85,-502.99 h60
  text "1.40mil" at 8313.62,-502.99 h60
  text "Bottom Solder" at 6524.11,-622.99 h60
  text "Solder Resist" at 7453.85,-622.99 h60
  text "0.40mil" at 8313.62,-622.99 h60
  text "3.5" at 8963.45,-622.99 h60
  text "Bottom Overlay" at 6524.11,-742.99 h60
  text ".Layer_Name" at 577,-2103.49 h60
M13 Component Bodies Top:
  text ".Layer_Name" at 577,-2103.49 h60
M14 Component Bodies Bottom:
  text ".Layer_Name" at 577,-2103.49 h60
M15 Courtyards Top:
  text ".Layer_Name" at 577,-2103.49 h60
M16 Courtyards Bottom:
  text ".Layer_Name" at 577,-2103.49 h60
Drill Drawing:
  drawing of 160 lines, arcs and shapes, not listed
  text "Symbol" at 6402.57,5837.63 h73.29
  text "Quantity" at 6708.19,5837.63 h73.29
  text "Finished Hole Size" at 7045.83,5837.63 h73.29
  text "Plated" at 7692.87,5837.63 h73.29
  text "Hole Type" at 7956.34,5837.63 h73.29
  text "Drill Layer Pair" at 8337.79,5837.63 h73.29
  text "Hole Tolerance" at 9073.93,5837.63 h73.29
  text "2" at 6708.19,5711.14 h61.07
  text "62.99mil (1.600mm)" at 7045.83,5711.14 h61.07
  text "NPTH" at 7692.87,5711.14 h61.07
  text "Round" at 7956.34,5711.14 h61.07
  text "Top Layer - Bottom Layer" at 8337.79,5711.14 h61.07
  text "2" at 6708.19,5584.65 h61.07
  text "86.61mil (2.200mm)" at 7045.83,5584.65 h61.07
  text "NPTH" at 7692.87,5584.65 h61.07
  text "Round" at 7956.34,5584.65 h61.07
  text "Top Layer - Bottom Layer" at 8337.79,5584.65 h61.07
  text "2" at 6708.19,5458.16 h61.07
  text "124.02mil (3.150mm)" at 7045.83,5458.16 h61.07
  text "NPTH" at 7692.87,5458.16 h61.07
  text "Round" at 7956.34,5458.16 h61.07
  text "Top Layer - Bottom Layer" at 8337.79,5458.16 h61.07
  text "C" at 6376.96,5448.17 h56.22
  text "397" at 6708.19,5331.66 h61.07
  text "7.87mil (0.200mm)" at 7045.83,5331.66 h61.07
  text "PTH" at 7692.87,5331.66 h61.07
  text "Round" at 7956.34,5331.66 h61.07
  text "Top Layer - Bottom Layer" at 8337.79,5331.66 h61.07
  text "B" at 6376.96,5321.67 h56.22
  text "2" at 6708.19,5205.17 h61.07
  text "27.56mil (0.700mm)" at 7045.83,5205.17 h61.07
  text "PTH" at 7692.87,5205.17 h61.07
  text "Round" at 7956.34,5205.17 h61.07
  text "Top Layer - Bottom Layer" at 8337.79,5205.17 h61.07
  text "+/-1.97mil" at 9073.93,5205.17 h61.07
  text "E" at 6376.96,5195.18 h56.22
  text "12" at 6708.19,5078.68 h61.07
  text "35.43mil (0.900mm)" at 7045.83,5078.68 h61.07
  text "PTH" at 7692.87,5078.68 h61.07
  text "Round" at 7956.34,5078.68 h61.07
  text "Top Layer - Bottom Layer" at 8337.79,5078.68 h61.07
  text "2" at 6708.19,4952.19 h61.07
  text "39.37mil (1.000mm)" at 7045.83,4952.19 h61.07
  text "PTH" at 7692.87,4952.19 h61.07
  text "Round" at 7956.34,4952.19 h61.07
  text "Top Layer - Bottom Layer" at 8337.79,4952.19 h61.07
  text "22" at 6708.19,4825.7 h61.07
  text "40.00mil (1.016mm)" at 7045.83,4825.7 h61.07
  text "PTH" at 7692.87,4825.7 h61.07
  text "Round" at 7956.34,4825.7 h61.07
  text "Top Layer - Bottom Layer" at 8337.79,4825.7 h61.07
  text "4" at 6708.19,4699.2 h61.07
  text "40.16mil (1.020mm)" at 7045.83,4699.2 h61.07
  text "PTH" at 7692.87,4699.2 h61.07
  text "Round" at 7956.34,4699.2 h61.07
  text "Top Layer - Bottom Layer" at 8337.79,4699.2 h61.07
  text "2" at 6708.19,4572.71 h61.07
  text "45.28mil (1.150mm)" at 7045.83,4572.71 h61.07
  text "PTH" at 7692.87,4572.71 h61.07
  text "Round" at 7956.34,4572.71 h61.07
  text "Top Layer - Bottom Layer" at 8337.79,4572.71 h61.07
  text "2" at 6708.19,4446.22 h61.07
  text "59.06mil (1.500mm)" at 7045.83,4446.22 h61.07
  text "PTH" at 7692.87,4446.22 h61.07
  text "Round" at 7956.34,4446.22 h61.07
  text "Top Layer - Bottom Layer" at 8337.79,4446.22 h61.07
  text "2" at 6708.19,4319.73 h61.07
  text "62.99mil (1.600mm)" at 7045.83,4319.73 h61.07
  text "PTH" at 7692.87,4319.73 h61.07
  text "Round" at 7956.34,4319.73 h61.07
  text "Top Layer - Bottom Layer" at 8337.79,4319.73 h61.07
  text "D" at 6376.96,4309.74 h56.22
  text "4" at 6708.19,4193.24 h61.07
  text "63.78mil (1.620mm)" at 7045.83,4193.24 h61.07
  text "PTH" at 7692.87,4193.24 h61.07
  text "Round" at 7956.34,4193.24 h61.07
  text "Top Layer - Bottom Layer" at 8337.79,4193.24 h61.07
  text "+/-1.97mil" at 9073.93,4193.24 h61.07
  text "F" at 6376.96,4183.25 h56.22
  text "8" at 6708.19,4066.74 h61.07
  text "66.93mil (1.700mm)" at 7045.83,4066.74 h61.07
  text "PTH" at 7692.87,4066.74 h61.07
  text "Round" at 7956.34,4066.74 h61.07
  text "Top Layer - Bottom Layer" at 8337.79,4066.74 h61.07
  text "2" at 6708.19,3940.25 h61.07
  text "98.43mil (2.500mm)" at 7045.83,3940.25 h61.07
  text "PTH" at 7692.87,3940.25 h61.07
  text "Round" at 7956.34,3940.25 h61.07
  text "Top Layer - Bottom Layer" at 8337.79,3940.25 h61.07
  text "4" at 6708.19,3813.76 h61.07
  text "125.98mil (3.200mm)" at 7045.83,3813.76 h61.07
  text "PTH" at 7692.87,3813.76 h61.07
  text "Round" at 7956.34,3813.76 h61.07
  text "Top Layer - Bottom Layer" at 8337.79,3813.76 h61.07
  text "2" at 6708.19,3687.27 h61.07
  text "23.62mil (0.600mm)" at 7045.83,3687.27 h61.07
  text "PTH" at 7692.87,3687.27 h61.07
  text "Slot" at 7956.34,3687.27 h61.07
  text "Top Layer - Bottom Layer" at 8337.79,3687.27 h61.07
  text "2" at 6708.19,3560.78 h61.07
  text "27.56mil (0.700mm)" at 7045.83,3560.78 h61.07
  text "PTH" at 7692.87,3560.78 h61.07
  text "Slot" at 7956.34,3560.78 h61.07
  text "Top Layer - Bottom Layer" at 8337.79,3560.78 h61.07
  text "3" at 6708.19,3434.28 h61.07
  text "31.50mil (0.800mm)" at 7045.83,3434.28 h61.07
  text "PTH" at 7692.87,3434.28 h61.07
  text "Slot" at 7956.34,3434.28 h61.07
  text "Top Layer - Bottom Layer" at 8337.79,3434.28 h61.07
  text "2" at 6708.19,3307.79 h61.07
  text "39.37mil (1.000mm)" at 7045.83,3307.79 h61.07
  text "PTH" at 7692.87,3307.79 h61.07
  text "Slot" at 7956.34,3307.79 h61.07
  text "Top Layer - Bottom Layer" at 8337.79,3307.79 h61.07
  text "A" at 6376.96,3297.8 h56.22
  text "2" at 6708.19,3181.3 h61.07
  text "39.37mil (1.000mm)" at 7045.83,3181.3 h61.07
  text "PTH" at 7692.87,3181.3 h61.07
  text "Slot" at 7956.34,3181.3 h61.07
  text "Top Layer - Bottom Layer" at 8337.79,3181.3 h61.07
  text "G" at 6376.96,3171.31 h56.22
  text "2" at 6708.19,3054.81 h61.07
  text "39.37mil (1.000mm)" at 7045.83,3054.81 h61.07
  text "PTH" at 7692.87,3054.81 h61.07
  text "Slot" at 7956.34,3054.81 h61.07
  text "Top Layer - Bottom Layer" at 8337.79,3054.81 h61.07
  text "H" at 6376.96,3044.82 h56.22
  text "482 Total" at 6708.19,2928.32 h61.07
  text "Slot definitions :" at 6402.57,2839.77 h61.07
  text "Routed Path Length" at 6860.43,2839.77 h61.07
  text "= Calculated from tool start centre position to tool end centre position." at 7408.91,2839.77 h61.07
  text "Hole Length" at 6860.43,2789.18 h61.07
  text "= Routed Path Length + Tool Size = Slot length as defined in the PCB layout" at 7205.87,2789.18 h61.07
  text ".Layer_Name" at 577,-2103.49 h60
Mechanical 17:
  text ".Layer_Name" at 577,-2103.49 h60
Mechanical 18:
  text ".Layer_Name" at 577,-2103.49 h60
Mechanical 19:
  text ".Layer_Name" at 577,-2103.49 h60

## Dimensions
0,-1245 to 4360,2.58 on M2 Board Dimensions
0,-1245 to 0,2205 on M2 Board Dimensions
0,-1645 to 1000,-1645 on M2 Board Dimensions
